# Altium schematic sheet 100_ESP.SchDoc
size A; SheetNumber: 3; SheetTotal: 5
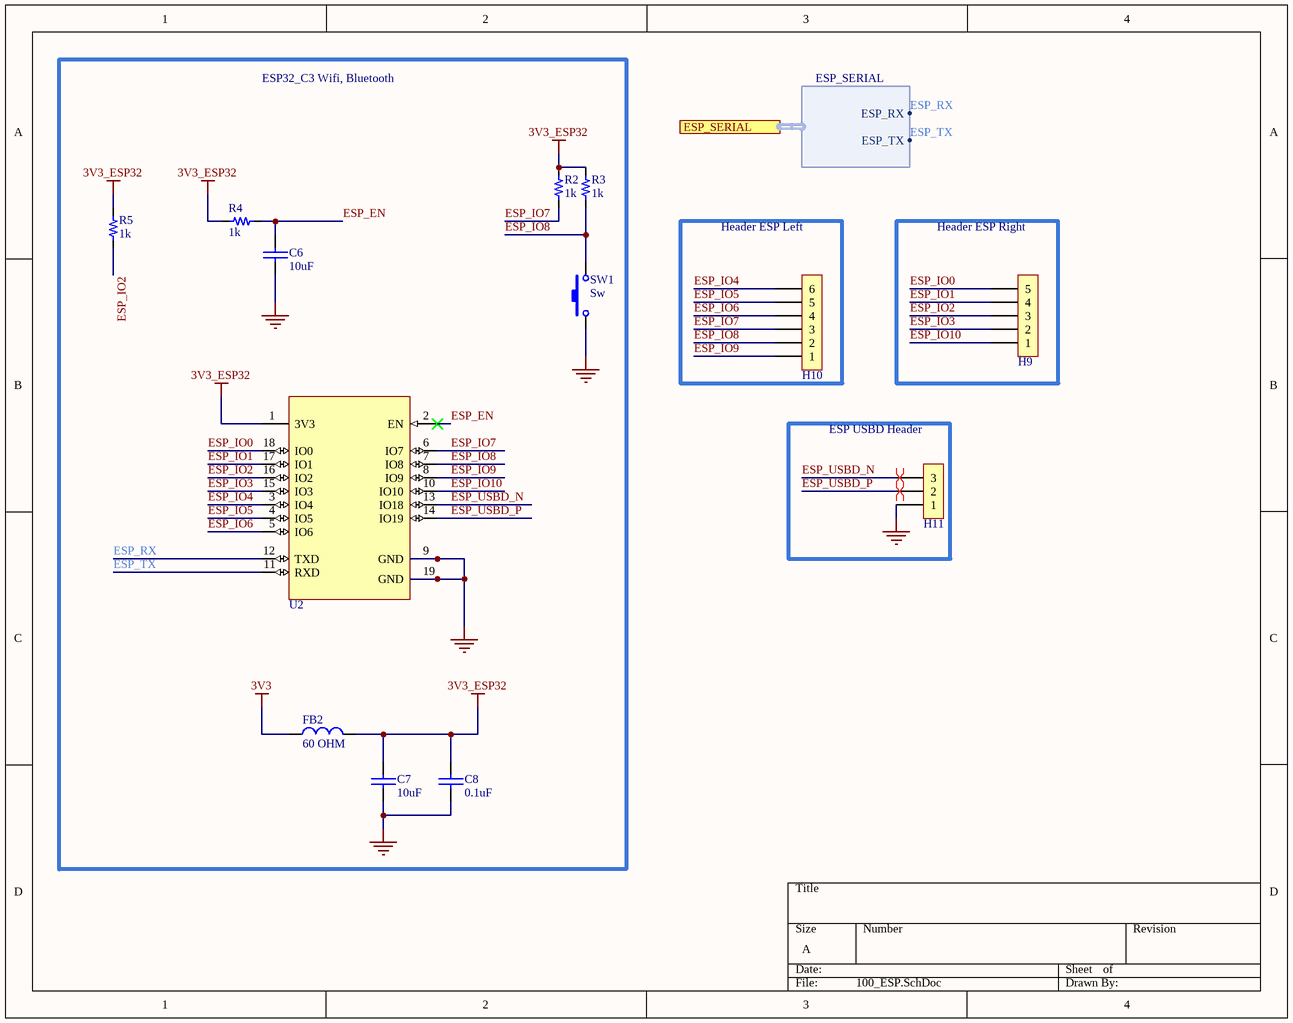
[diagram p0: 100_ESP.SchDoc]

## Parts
C6  value 10uF  [0805_cap]  (hidden comment: 10uF 25V)
C7  value 10uF  [0805_cap]  (hidden comment: 10uF 25V)
C8  value 0.1uF  [0603_cap]  (hidden comment: 0.1uF 50V)
FB2  value 60 OHM  [0603_fb]  (hidden comment: 60OHM 2A)
H9  5x1  [H_5x1_TH_100mil]  (value not drawn)  (no BOM)
H10  6x1  [H_6x1_TH_100mil]  (value not drawn)  (no BOM)
H11  3x1  [H_3X1_TH_100mil]  (value not drawn)  (no BOM)
R2  value 1k  [0603_res]  (hidden comment: 1k 1/10W)
R3  value 1k  [0603_res]  (hidden comment: 1k 1/10W)
R4  value 1k  [0603_res]  (hidden comment: 1k 1/10W)
R5  value 1k  [0603_res]  (hidden comment: 1k 1/10W)
SW1  Sw  [Sw_PUSH_4.5x4.5x5mm]
U2  ESP32-C3-WROOM-02-N4  [ESP32-C3-WROOM-02-N4]  (value not drawn)

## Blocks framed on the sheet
ESP32_C3 Wifi, Bluetooth: C6-C8 FB2 R2-R5 SW1 U2
Header ESP Left: H10
Header ESP Right: H9
ESP USBD Header: H11

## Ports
ESP_SERIAL (harness ESP_SERIAL, see Main[2B], 000_STM[3C])

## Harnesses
ESP_SERIAL: ESP_RX, ESP_TX

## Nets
3V3: FB2.1
3V3_ESP32: C7.1 C8.1 FB2.2 R2.2 R3.2 R4.2 R5.2 U2.1(3V3)
GND: C6.2 C7.2 C8.2 H11.1 SW1.1 U2.9(GND) U2.19(GND)
ESP_EN: C6.1 R4.1 U2.2(EN)
ESP_IO0: H9.5 U2.18(IO0)
ESP_IO1: H9.4 U2.17(IO1)
ESP_IO2: H9.3 R5.1 U2.16(IO2)
ESP_IO3: H9.2 U2.15(IO3)
ESP_IO4: H10.6 U2.3(IO4)
ESP_IO5: H10.5 U2.4(IO5)
ESP_IO6: H10.4 U2.5(IO6)
ESP_IO7: H10.3 R2.1 U2.6(IO7)
ESP_IO8: H10.2 R3.1 SW1.2 U2.7(IO8)
ESP_IO9: H10.1 U2.8(IO9)
ESP_IO10: H9.1 U2.10(IO10)
ESP_RX: U2.12(TXD) ; port ESP_SERIAL.ESP_RX
ESP_TX: U2.11(RXD) ; port ESP_SERIAL.ESP_TX
ESP_USBD_N: H11.3 U2.13(IO18)
ESP_USBD_P: H11.2 U2.14(IO19)

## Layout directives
differential pair; differential pair class USB_2.0_ESP: ESP_USBD_N, ESP_USBD_P

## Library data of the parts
C6 C7 = Cap_10uF_0805_25V_: 25V 10uF X5R ±10% 0805 Multilayer Ceramic Capacitors MLCC - SMD/SMT ROHS; Manufacturer: Samsung Electro-Mechanics; Manufacturer Part Number: CL21A106KAYNNNE
C8 = Cap_0.1uF_0603_50V: 50V 100nF Y5V -20%~+80% 0603 Multilayer Ceramic Capacitors MLCC - SMD/SMT ROHS; Manufacturer: Walsin Tech Corp; Manufacturer Part Number: 0603F104Z500CT
FB2 = FB_60_0603_2A: 2A 1 100mΩ 60Ω@100MHz ±25% 0603 Ferrite Beads ROHS; Manufacturer: TAI-TECH; Manufacturer Part Number: HCB1608KF-600T20
H9 = H_Male_5x1_TH_100mil
H10 = H_Male_6x1_TH_100mil
H11 = H_Male_3x1_TH_100mil
R2-R5 = Res_1k_0603_1/10W: RES SMD 1k OHM 5% 1/10W 0603; Manufacturer: FOJAN; Manufacturer Part Number: FRC0603J102 TS
SW1 = Sw_PUSH_4.5x4.5x5.0xmm: SWITCH TACTILE SPST-NO 0.05A 12V; Manufacturer: BZCN; Manufacturer Part Number: TSC015A05026A
U2 = MCU_ESP32-C3-WROOM-02-N4: RF TXRX MOD BT WIFI PCB TH SMD; Manufacturer: Espressif Systems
